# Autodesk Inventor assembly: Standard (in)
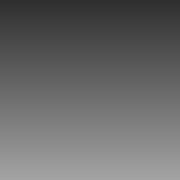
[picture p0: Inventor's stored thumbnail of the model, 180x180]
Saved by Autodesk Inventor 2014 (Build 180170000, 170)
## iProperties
Shininess: 64.0
Length Units: 11272
Angle Units: 11279
Time Units: 11290
Mass Units: 11286
Length Display Precision: 3
Angle Display Precision: 2
Compacted: True
Part Number: Standard (in)
Document SubType Name: Assembly
Created: 2002-07
Designer: invbi
Density: 0.0
Volumn: 0.0
Area: 0.0
PropertySet Name: Model Information
Control State: 0
Master: False
Checked Out: False
Author: invbi
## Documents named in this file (1)
- B:\VRTC_DWG\Inventor Support Files\Templates\Standard.iam
